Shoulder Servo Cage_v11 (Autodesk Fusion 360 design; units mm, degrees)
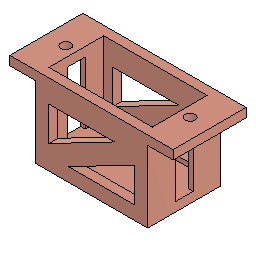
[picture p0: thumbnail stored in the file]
sketch "Sketch1" plane through (0, 0, 0) normal (0, 0, 1) x axis (1, 0, 0)
  line L1 (-11.4, -6.05) -> (11.4, -6.05)
  line L2 (-11.4, 6.05) -> (-11.4, -6.05)
  line L3 (11.4, 6.05) -> (-11.4, 6.05)
  line L4 (11.4, -6.05) -> (11.4, 6.05)
  line L5 (-11.4, 6.05) -> (11.4, -6.05)
  line L6 (11.4, 6.05) -> (-11.4, -6.05)
  line L7 (-16, 6) -> (-16.0091, -6.1)
  line L8 (15.9907, -5.9965) -> (15.9999, 6.0965)
  line L9 (-16, 6) -> (15.9907, -5.9965)
  line L10 (15.9999, 6.0965) -> (-16.0091, -6.1)
  line L11 (-13.4, 8.05) -> (13.4, 8.05)
  line L12 (-13.4, -8.05) -> (-13.4, 8.05)
  line L13 (13.4, -8.05) -> (-13.4, -8.05)
  line L14 (13.4, 8.05) -> (13.4, -8.05)
  line L15 (-13.4, -8.05) -> (13.4, 8.05)
  line L16 (13.4, -8.05) -> (-13.4, 8.05)
  line L17 (-15.9958, 8.0479) -> (16.0042, 8.0479)
  line L18 (-15.9958, -8.0521) -> (-15.9958, 8.0479)
  line L19 (16.0042, -8.0521) -> (-15.9958, -8.0521)
  line L20 (16.0042, 8.0479) -> (16.0042, -8.0521)
  line L21 (16.0042, -8.0521) -> (-15.9958, 8.0479)
  line L22 (11.4, 6.05) -> (-11.4, 6.05)
  line L23 (-11.4, -6.05) -> (11.4, -6.05)
  line L24 (-13.4, -6.7384) -> (16.0042, 8.0479)
  point P6 (0, 0)
  point P1 (0, 0)
  point P11 (0, 0)
  point P16 (0, 0)
  point P21 (0, 0)
  point P22 (-13.4, -6.7384)
  point P4 (-11.4, 6.05)
  point P5 (11.4, 6.05)
  point P3 (-11.4, -6.05)
  point P9 (-16, 6)
  point P10 (15.9999, 6.0965)
  point P8 (-16.0091, -6.1)
  point P14 (-13.4, -8.05)
  point P15 (13.4, -8.05)
  point P19 (-15.9958, -8.0521)
  point P20 (16.0042, -8.0521)
  point P18 (-15.9958, 8.0479)
  point P13 (-13.4, 8.05)
  horizontal L1
  perpendicular L1 L2
  parallel L1 L3
  parallel L2 L4
  coincident L5 P6
  coincident L6 P6
  coincident P1 P6
  parallel L7 L8
  coincident L9 P11
  coincident L10 P11
  coincident P6 P11
  horizontal L11
  perpendicular L11 L12
  parallel L11 L13
  parallel L12 L14
  coincident L15 P16
  coincident L16 P16
  coincident P1 P16
  horizontal L17
  perpendicular L17 L18
  parallel L17 L19
  parallel L18 L20
  coincident P21 L24
  coincident L21 P21
  coincident P16 P21
  coincident L12 P22
  dimension "d1" distance P4 P5 = 22.8
  dimension "d2" distance P3 P4 = 12.1
  dimension "d3" distance P9 P10 = 32
  dimension "d4" distance P8 P9 = 12.1
  dimension "d5" distance P14 P15 = 26.8 (= "d1 + 4 mm")
  dimension "d7" distance P19 P20 = 32
  dimension "d39" distance P18 P19 = 16.1 (= "d2 + 4 mm")
  dimension "d40" distance P13 P14 = 16.1 (= "d2 + 4 mm")
extrude "Extrude1" new body sketch "Sketch1" profile of L1 L2 L3 L4 L23 L22 along normal blind 2
extrude "Extrude2" add sketch "Sketch1" profile of L1 L2 L3 L4 L23 L22 L11 L12 L13 L14 L17 L19 along normal blind 17.8 (= "15.8 mm + 2 mm")
sketch "Sketch2" plane through (13.4, 0, 0) normal (1, 0, 0) x axis (0, 1, 0)
  line L1 (8.0479, 0) -> (-8.05, 0)
  line L2 (8.0479, 17.8) -> (8.0479, 0)
  line L3 (-8.05, 17.8) -> (8.0479, 17.8)
  line L4 (-8.05, 0) -> (-8.05, 17.8)
  line L5 (8.05, 17.8) -> (-8.05, 17.8)
  line L6 (8.05, 15.8) -> (8.05, 17.8)
  line L7 (-8.05, 15.8) -> (8.05, 15.8)
  line L8 (-8.05, 17.8) -> (-8.05, 15.8)
  point P5 (-8.05, 17.8)
  point P6 (-8.05, 17.8)
  point P9 (-8.05, 15.8)
  point P8 (8.05, 15.8)
  horizontal L5
  vertical L6
  horizontal L7
  vertical L8
  coincident P5 P6
  dimension "d13" distance P6 P9 = 2
  dimension "d41" distance P8 P9 = 16.1 (= "12.1 mm + 4 mm")
extrude "Extrude3" add sketch "Sketch2" profile of L2 L3 L4 L5 L6 L7 L8 along normal blind 4.6 (= "( ( 32 - 4 - 22.8 ) / 2 ) * 1 mm + 2 mm")
sketch "Sketch3" plane through (0, 0, 17.8) normal (0, 0, 1) x axis (-1, 0, 0)
  line L1 (-11.4, 6.05) -> (-11.4, -6.05)
  line L2 (11.4, 6.05) -> (-11.4, 6.05)
  line L3 (11.4, -6.05) -> (11.4, 6.05)
  line L4 (-11.4, -6.05) -> (11.4, -6.05)
  line L5 (13.4, 8.05) -> (13.4, -8.0479)
  line L6 (-18, 8.05) -> (13.4, 8.05)
  line L7 (13.4, -8.0479) -> (-13.4, -8.0479)
  line L8 (-18, -8.05) -> (-18, 8.05)
  line L9 (-13.4, -8.05) -> (-18, -8.05)
  line L10 (-13.4, -8.0479) -> (-13.4, -8.05)
  circle C1 centre (-13.7, 0) radius 1.1
  point P10 (-13.7, 0)
  dimension "d16" diameter C1 = 2.2
  dimension "d17" distance L1 P10 = 2.3
extrude "Extrude4" cut sketch "Sketch3" profile of C1 against normal blind 2
mirror "Mirror1" mirrorStitchTolerance 0.1
sketch "Sketch4" plane through (-13.4, 0, 0) normal (-1, 0, 0) x axis (0, -1, 0)
  line L1 (8.05, 0) -> (-8.0479, 0)
  line L2 (8.05, 15.8) -> (8.05, 0)
  line L3 (8.05, 8.9) -> (-8, 8.9)
  line L4 (-1.975, 2) -> (2.025, 2)
  line L5 (-1.975, 15.8) -> (-1.975, 2)
  line L6 (2.025, 15.8) -> (-1.975, 15.8)
  line L7 (2.025, 2) -> (2.025, 15.8)
  line L8 (-1.975, 15.8) -> (2.025, 2)
  line L9 (2.025, 15.8) -> (-1.975, 2)
  line L10 (0, 0) -> (0.025, 8.9)
  line L11 (8.05, 7) -> (-7, 7)
  line L12 (-1.0583, 15.8) -> (1.0583, 15.8)
  line L13 (-8.0479, 0) -> (-8.0479, 15.8)
  line L14 (1.0583, 15.8) -> (8.05, 15.8)
  line L15 (-8.0479, 15.8) -> (-1.0583, 15.8)
  point P6 (8.05, 8.9)
  point P11 (0.025, 8.9)
  point P12 (0.025, 8.9)
  point P1 (0, 0)
  point P13 (0, 0)
  point P15 (8.05, 7)
  point P16 (0.525, 7)
  point P9 (-1.975, 15.8)
  point P10 (2.025, 15.8)
  point P8 (-1.975, 2)
  coincident L2 P6
  perpendicular L2 L3
  horizontal L4
  perpendicular L4 L5
  parallel L4 L6
  parallel L5 L7
  coincident L8 P11
  coincident L9 P11
  midpoint L3 P11
  coincident P11 P12
  coincident P1 P13
  coincident L2 P15
  perpendicular L2 L11
  midpoint L11 P16
  dimension "d22" distance L1 L3 = 8.9 (= "( 15.8 / 2 ) * 1 mm + 1 mm")
  dimension "d23" distance P9 P10 = 4
  dimension "d24" distance P8 P9 = 13.8 (= "15.8 mm - 2 mm")
  dimension "d31" distance L1 L11 = 7
extrude "Extrude5" cut sketch "Sketch4" profile of L4 L5 L6 L7 against normal blind 2
extrude "Extrude6" cut sketch "Sketch4" profile of L5 L7 against normal blind 1
mirror "Mirror2" mirrorStitchTolerance 0.1
mirror "Mirror3" mirrorStitchTolerance 0.1
sketch "Sketch5" plane through (0, -8.05, 0) normal (0, -1, 0) x axis (1, 0, 0)
  line L1 (12.4, 15.8) -> (12.4, 0)
  line L2 (18, 15.8) -> (12.4, 15.8)
  line L3 (18, 17.8) -> (18, 15.8)
  line L4 (-18, 17.8) -> (18, 17.8)
  line L5 (-18, 15.8) -> (-18, 17.8)
  line L6 (-12.4, 15.8) -> (-18, 15.8)
  line L7 (-12.4, 0) -> (-12.4, 15.8)
  line L8 (12.4, 0) -> (-12.4, 0)
  line L9 (-12.4, 15.8) -> (12.4, 15.8)
  line L10 (0, 0) -> (0, 15.8)
  line L11 (-9.4, 3) -> (9.4, 3)
  line L12 (-9.4, 12.8) -> (-9.4, 3)
  line L13 (9.4, 12.8) -> (-9.4, 12.8)
  line L14 (9.4, 3) -> (9.4, 12.8)
  line L15 (-9.4, 12.8) -> (9.4, 3)
  line L16 (9.4, 12.8) -> (-9.4, 3)
  line L17 (-5.0733, 3) -> (9.4, 10.5446)
  line L18 (-9.4, 5.2554) -> (5.0733, 12.8)
  point P3 (12.4, 15.8)
  point P10 (12.4, 15.8)
  point P8 (-12.4, 15.8)
  point P11 (-12.4, 15.8)
  point P12 (0, 15.8)
  point P1 (0, 0)
  point P13 (0, 0)
  point P18 (0, 7.9)
  point P19 (5.0733, 12.8)
  point P20 (9.4, 10.5446)
  point P21 (-5.0733, 3)
  point P22 (-9.4, 5.2554)
  point P16 (-9.4, 12.8)
  point P17 (9.4, 12.8)
  point P15 (-9.4, 3)
  coincident P3 P10
  coincident P8 P11
  midpoint L9 P12
  coincident P1 P13
  horizontal L11
  perpendicular L11 L12
  parallel L11 L13
  parallel L12 L14
  coincident L15 P18
  coincident L16 P18
  midpoint L10 P18
  parallel L16 L18
  parallel L16 L17
  coincident L13 P19
  coincident L14 P20
  coincident L11 P21
  coincident L12 P22
  dimension "d44" distance P16 P17 = 18.8 (= "24.8 mm - 6 mm")
  dimension "d45" distance P15 P16 = 9.8 (= "15.8 mm - 6 mm")
  dimension "d46" distance L16 L18 = 2
  dimension "d47" distance L16 L17 = 2
extrude "Extrude7" cut sketch "Sketch5" profile of L11 L12 L13 L14 L17 L18 against normal blind 2
mirror "Mirror4" mirrorStitchTolerance 0.1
